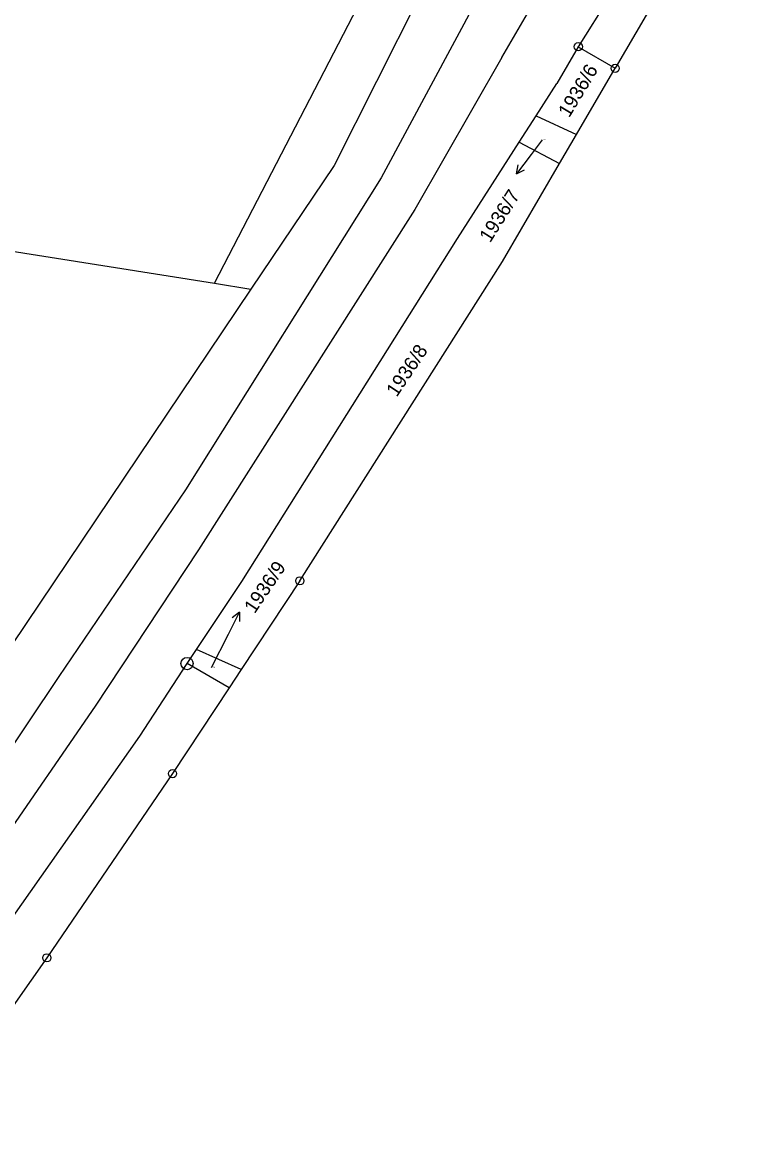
# Model space of a CAD drawing. Extents: x -795483 to -789093, y -1112258 to -1108741.
# Drawn here: x -792118.6 to -792029.2, y -1111384.1 to -1111247.6 of the extents above; entities that cross this region are included whole.
import ezdxf

# ---------------------------------------------------------------- set-up
doc = ezdxf.new("R2010")
doc.units = 0
for name, color, linetype in [('Komunikace', 7, 'Continuous'), ('Vrstva 1', 7, 'Continuous'), ('Vrstva 14', 7, 'Continuous'), ('Vrstva 16', 7, 'Continuous'), ('Vrstva 2', 7, 'Continuous'), ('Vrstva 28', 7, 'Continuous'), ('Vrstva 4', 7, 'Continuous')]:
    doc.layers.add(name, color=color, linetype=linetype)

msp = doc.modelspace()

# ---------------------------------------------------------------- linework, layer by layer
at = {"layer": 'Komunikace'}
for p, q in [((-792055.11, -1111262.03), (-792056.45, -1111263.79)), ((-792095.52, -1111326.56), (-792093.45, -1111322.47))]:
    msp.add_line(p, q, dxfattribs=at)
at = {"layer": 'Vrstva 1'}
for p, q in [((-792095.15, -1111279.56), (-792050.87, -1111193.86)), ((-792055.66, -1111215.64), (-792080.54, -1111265.16)), ((-792053.01, -1111226.15), (-792074.81, -1111266.65)), ((-792038.5, -1111231.2), (-792050.71, -1111250.62)), ((-792050.71, -1111250.62), (-792053.32, -1111255.13)), ((-792050.71, -1111250.62), (-792046.2, -1111253.26)), ((-792245.78, -1111255.62), (-792095.15, -1111279.56)), ((-792055.86, -1111259.09), (-792053.32, -1111255.13)), ((-792057.91, -1111262.28), (-792055.86, -1111259.09)), ((-792055.86, -1111259.09), (-792050.94, -1111261.38)), ((-792065.48, -1111274.08), (-792057.91, -1111262.28)), ((-792057.91, -1111262.28), (-792053, -1111264.92)), ((-792080.54, -1111265.16), (-792090.71, -1111280.28)), ((-792074.81, -1111266.65), (-792098.71, -1111304.83)), ((-792091.83, -1111316.01), (-792065.48, -1111274.08)), ((-792090.71, -1111280.28), (-792130.63, -1111339.66)), ((-792095.15, -1111279.56), (-792090.71, -1111280.28)), ((-792098.71, -1111304.83), (-792114.2, -1111327.66)), ((-792097.37, -1111324.34), (-792091.83, -1111316.01)), ((-792098.52, -1111326.07), (-792097.37, -1111324.34)), ((-792091.89, -1111326.8), (-792097.37, -1111324.34)), ((-792104.27, -1111334.95), (-792098.52, -1111326.07)), ((-792093.38, -1111329.05), (-792098.52, -1111326.07)), ((-792114.2, -1111327.66), (-792129.08, -1111349.91)), ((-792120.03, -1111357.39), (-792104.27, -1111334.95))]:
    msp.add_line(p, q, dxfattribs=at)
at = {"layer": 'Vrstva 16'}
for p, q in [((-792056.45, -1111263.79), (-792058.27, -1111266.17)), ((-792058.27, -1111266.17), (-792058.06, -1111265.08)), ((-792058.27, -1111266.17), (-792057.27, -1111265.68)), ((-792093.45, -1111322.47), (-792092.1, -1111319.79)), ((-792092.1, -1111319.79), (-792092.99, -1111320.46)), ((-792092.1, -1111319.79), (-792092.1, -1111320.91))]:
    msp.add_line(p, q, dxfattribs=at)
at = {"layer": 'Vrstva 2'}
for p, q in [((-792060.03, -1111251.95), (-792050.59, -1111235.64)), ((-792060.03, -1111251.95), (-792070.66, -1111270.54)), ((-792070.66, -1111270.54), (-792097.1, -1111312.16)), ((-792097.1, -1111312.16), (-792109.74, -1111331.28)), ((-792109.74, -1111331.28), (-792124.43, -1111352.62))]:
    msp.add_line(p, q, dxfattribs=at)
at = {"layer": 'Vrstva 28'}
for centre, radius in [((-792050.71, -1111250.62), 0.5), ((-792050.71, -1111250.62), 0.01), ((-792046.2, -1111253.26), 0.5), ((-792046.2, -1111253.26), 0.01), ((-792084.73, -1111315.95), 0.5), ((-792084.73, -1111315.95), 0.01), ((-792098.52, -1111326.07), 0.75), ((-792098.52, -1111326.07), 0.01), ((-792100.3, -1111339.53), 0.5), ((-792100.3, -1111339.53), 0.01), ((-792115.65, -1111362.06), 0.5), ((-792115.65, -1111362.06), 0.01)]:
    msp.add_circle(centre, radius, dxfattribs=at)
at = {"layer": 'Vrstva 4'}
for p, q in [((-792029.15, -1111224.02), (-792046.2, -1111253.26)), ((-792050.94, -1111261.38), (-792046.2, -1111253.26)), ((-792053, -1111264.92), (-792050.94, -1111261.38)), ((-792059.98, -1111276.89), (-792053, -1111264.92)), ((-792084.73, -1111315.95), (-792059.98, -1111276.89)), ((-792084.73, -1111315.95), (-792091.89, -1111326.8)), ((-792091.89, -1111326.8), (-792093.38, -1111329.05)), ((-792093.38, -1111329.05), (-792100.3, -1111339.53)), ((-792100.3, -1111339.53), (-792115.65, -1111362.06)), ((-792115.65, -1111362.06), (-792131.1, -1111384.05))]:
    msp.add_line(p, q, dxfattribs=at)

# ---------------------------------------------------------------- texts
at = {"layer": 'Vrstva 14'}
for s, rotation, p in [('1936/6', 58.9577, (-792051.82, -1111259.39)), ('1936/8', 56.2464, (-792072.89, -1111293.55))]:
    msp.add_text(s, height=1.7, rotation=rotation, dxfattribs=at).set_placement(p)
for s, p in [('1936/7', (-792055.11, -1111262.03)), ('1936/9', (-792095.52, -1111326.56))]:
    msp.add_text(s, height=0.1, dxfattribs=at).set_placement(p)
at = {"layer": 'Vrstva 16'}
for s, rotation, p in [('1936/7', 57.6084, (-792061.48, -1111274.68)), ('1936/9', 55.8888, (-792090.26, -1111320.05))]:
    msp.add_text(s, height=1.7, rotation=rotation, dxfattribs=at).set_placement(p)

doc.saveas('drawing.dxf')
